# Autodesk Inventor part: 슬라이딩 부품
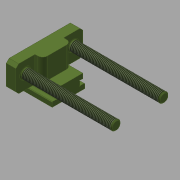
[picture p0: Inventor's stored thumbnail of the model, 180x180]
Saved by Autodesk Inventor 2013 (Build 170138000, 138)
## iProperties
Created: 2017-04
Part Number: 슬라이딩 부품
Material: 강철, 연강
Document SubType Name: Modeling
Designer: mduedu
Density: 1 g/cm^3
Author: mduedu
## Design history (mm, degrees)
sketch "스케치1"
  geometry: L1 (37, 35)-(10, 35); L2 (0, 17)-(0, 0); L3 (0, 17)-(5, 17); L4 (5, 17)-(5, 12); L5 (5, 12)-(10, 12); L6 (10, 12)-(10, 35); L7 (37, 35)-(37, 0); L8 (37, 0)-(0, 0); L9 (37, -35)-(10, -35); L10 (0, -17)-(0, 0); L11 (0, -17)-(5, -17); L12 (5, -17)-(5, -12); L13 (5, -12)-(10, -12); L14 (10, -12)-(10, -35); L15 (37, -35)-(37, 0)
  constraints: 30 end point, 6 symmetric about line, 3 perpendicular, 2 horizontal, 2 point on line, 2 vertical
  dimensions: "d39" = 5 distance of L2.start L3.end; "d41" = 70 distance between parallel lines of L9 L1; "d42" = 27 distance of L9.start L9.end; "d43" = 24 distance between parallel lines of L13 L5; "d44" = 5 distance of L4.end L5.end; "d45" = 34 distance between parallel lines of L11 L3
extrude "돌출1" new body sketch "스케치1" distance "d5" = 10; taper "d6" = 0 deg
sketch "스케치2"
  geometry: L1 (-35, 10)-(-35, 37) reference; L2 (17, 0)-(-17, 0) reference; L3 (-17, 0)-(-17, 5) reference; L4 (-17, 5)-(-12, 5) reference; L5 (-12, 5)-(-12, 10) reference; L6 (-12, 10)-(-35, 10) reference; L7 (-35, 37)-(35, 37) reference; L8 (35, 37)-(35, 10) reference; L9 (35, 10)-(12, 10) reference; L10 (12, 10)-(12, 5) reference; L11 (12, 5)-(17, 5) reference; L12 (17, 5)-(17, 0) reference; L13 (-12, 10)-(-15, 10); L14 (-15, 10)-(-15, 15); L15 (-15, 15)-(15, 15); L16 (15, 15)-(15, 10); L17 (15, 10)-(12, 10)
  constraints: 10 end point, 4 perpendicular, 2 point on line
  dimensions: "d46" = 3 distance between parallel lines of L14 L5; "d47" = 3 distance between parallel lines of L16 L10 (= d46); "d48" = 5 distance of L13.end L14.end
extrude "돌출2" join sketch "스케치2" distance "d12" = 20; taper "d13" = 0 deg
sketch "스케치3"
  geometry: L1 (0, 20)-(8, 20); L2 (8, 20)-(8, 50); L3 (8, 50)-(0, 50); L4 (0, 50)-(0, 20); L5 (0, 50)-(20, 50) reference; L6 (0, 20)-(20, 20) reference; L7 (0, 0)-(0, 70) reference; 2 further points
  constraints: 8 end point, 2 midpoint, 2 parallel, 1 horizontal, 1 perpendicular, 1 point on line
  dimensions: "d14" = 8 distance between parallel lines of L2 L4
extrude "돌출3" join sketch "스케치3" stored distance "d16" = 20; taper "d17" = 0 deg
fillet "모깎기1" dims "d18" = 5
sketch "스케치4"
  geometry: L1 (-15, 10)-(-35, 10) reference; L2 (-35, 10)-(-35, 37) reference; C1 r 5 at (-25, 25); 1 further point
  constraints: 1 centre point
  dimensions: "d19" = 10 diameter of C1; "d23" = 25 horizontal distance of point (0, 0) C1.centre (derived); "d49" = 15 distance from line of C1.centre L1; "d50" = 10 distance from line of C1.centre L2
extrude "돌출4" join sketch "스케치4" distance "d24" = 95; taper "d25" = 0 deg
feature "스레드1" dims "d26" = 10, "d27" = 0
chamfer "모따기1" distance "d28" = 1; stored, may be unused: second distance "d29" = 2, angle "d30" = 45 deg
fillet "모깎기2" dims "d31" = 1
sketch "스케치5"
  geometry: L1 (-12, 5)-(-12, 10) reference; L2 (12, 10)-(12, 5) reference; C1 r 0.5 at (-12, 10); C2 r 0.5 at (-12, 5); C3 r 0.5 at (12, 5); C4 r 0.5 at (12, 10); 1 further point
  constraints: 4 centre point, 4 coincident, 3 equal radius
  dimensions: "d51" = 1 diameter of C1
extrude "돌출5" cut sketch "스케치5" stored distance "d34" = 89; taper "d35" = 0 deg
chamfer "모따기2" distance "d36" = 3; stored, may be unused: second distance "d37" = 2, angle "d38" = 45 deg
chamfer "모따기3" distance "d52" = 0.5; stored, may be unused: second distance "d53" = 2, angle "d54" = 45 deg
mirror "대칭2"
node "솔리드2"
node "투영된 루프1"
node "솔리드1"
